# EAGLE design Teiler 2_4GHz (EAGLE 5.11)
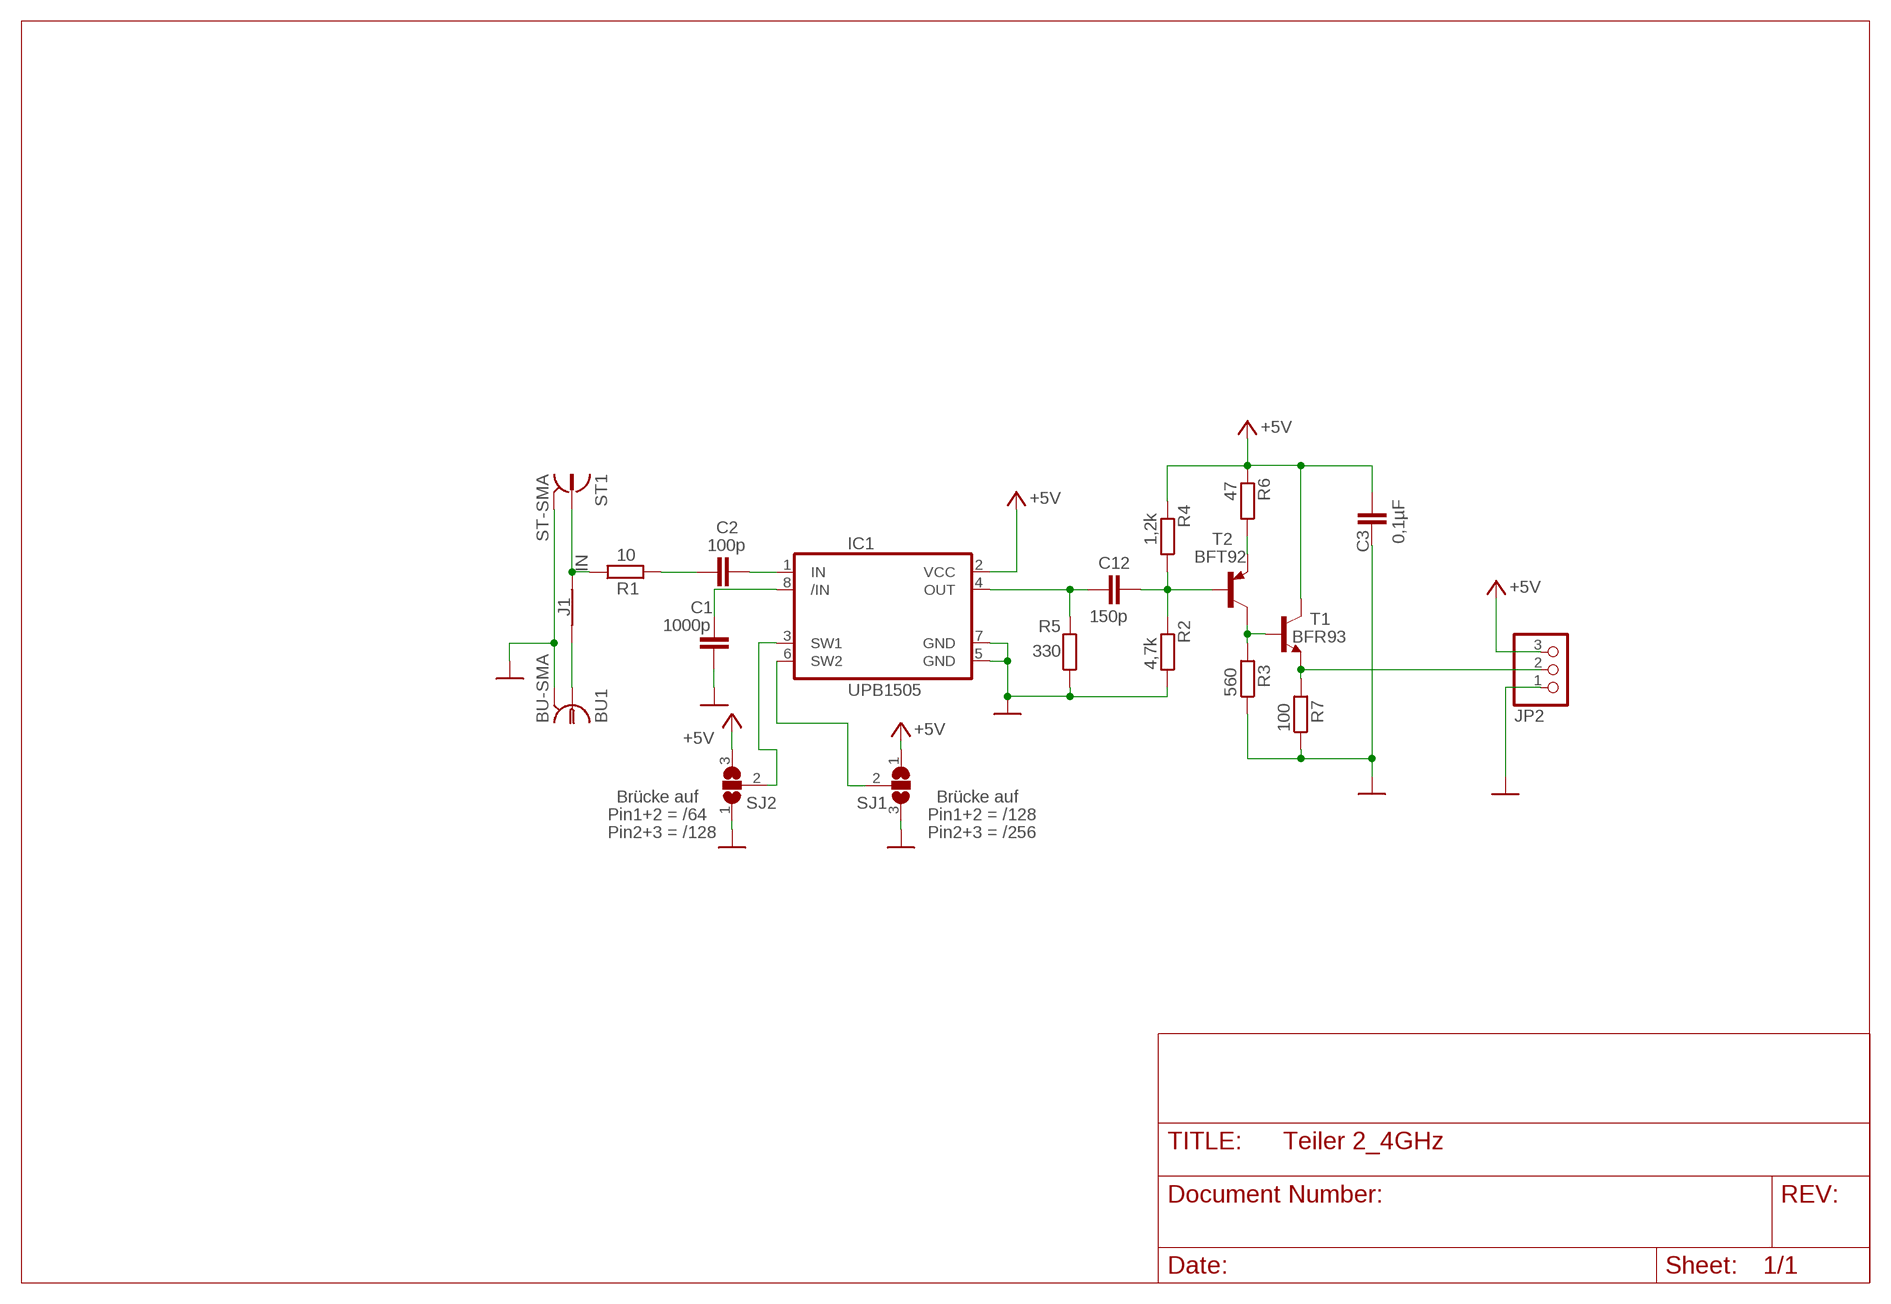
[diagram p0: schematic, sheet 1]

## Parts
BU1  BU-SMA  BU.SMA-L  [BU-SMA-L]
C1  1000p  C-EUC0805  [C0805]
C2  100p  C-EUC0805  [C0805]
C3  0,1µF  C-EUC0805  [C0805]
C12  150p  C-EUC0805  [C0805]
IC1  UPB1505  [SO8]
J1  IN  VORTEILER_IN  [VORT_JUMPER]
JP2  PINHD-1X03_2.54-SMD-90°  [1X03SMD/90]
R1  10  R-EU_M1206  [M1206]
R2  4,7k  R-EU_R0805  [R0805]
R3  560  R-EU_R0805  [R0805]
R4  1,2k  R-EU_R0805  [R0805]
R5  330  R-EU_R0805  [R0805]
R6  47  R-EU_R0805  [R0805]
R7  100  R-EU_R0805  [R0805]
SJ1  SJ2W  [SJ_2]
SJ2  SJ2W  [SJ_2]
ST1  ST-SMA  ST-BNC-L  [ST-SMA-L]
T1  BFR93  BFR93-NPN-SOT23-BEC  [SOT23-BEC]
T2  BFT92  BC807-16-PNP-SOT23-BEC  [SOT23-BEC]

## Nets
+5V: C3.1 IC1.2(VCC) JP2.3 R4.2 R6.2 SJ1.1 SJ2.3 T1.C
GND: BU1.GND C1.1 C3.2 IC1.5(GND) IC1.7(GND) JP2.1 R2.1 R3.1 R5.1 R7.1 SJ1.3 SJ2.1 ST1.GND
N$1: C1.2 IC1.8(/IN)
N$2: C12.2 IC1.4(OUT) R5.2
N$3: BU1.1 J1.GND@1
N$4 [Abstand1]: J1.GND@2 R1.1 ST1.1
N$5: C2.1 IC1.1(IN)
N$6: C12.1 R2.2 R4.1 T2.B
N$8: C2.2 R1.2
N$9: R3.2 T1.B T2.C
N$10: IC1.6(SW2) SJ1.2
N$11: R6.1 T2.E
N$12: IC1.3(SW1) SJ2.2
OUT: JP2.2 R7.2 T1.E

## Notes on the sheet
- Brücke auf | Brücke auf
- Pin1+2 = /64 | Pin1+2 = /128
- Pin2+3 = /128 | Pin2+3 = /256

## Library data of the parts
BU1 = 1Eigene:BU.SMA-L
C1-C3 C12 = rcl:C-EU: CAPACITOR, European symbol
IC1 = 1Eigene:UPB1505
J1 = 1Eigene:VORTEILER_IN
JP2 = pinhead-2:PINHD-1X03: PIN HEADER
R1-R7 = rcl:R-EU_: RESISTOR, European symbol
SJ1 SJ2 = jumper:SJ2W: SMD solder JUMPER
ST1 = 1Eigene:ST-BNC-L
T1 = transistor-neu-to92:*-NPN-: NPN Transistror
T2 = transistor:*-PNP-: PNP Transistror

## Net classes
1 Abstand1: width 0.1 mm, drill 0.6 mm, clearance 2 mm

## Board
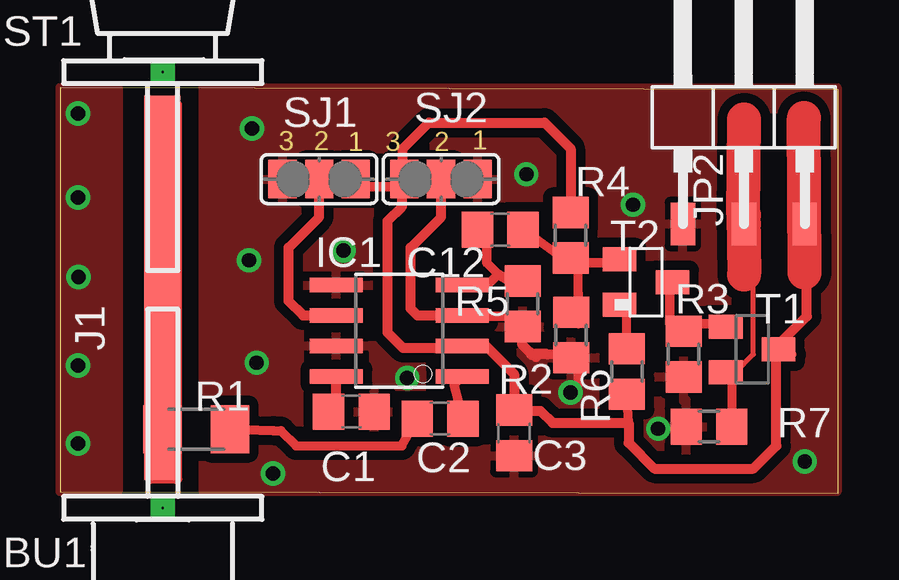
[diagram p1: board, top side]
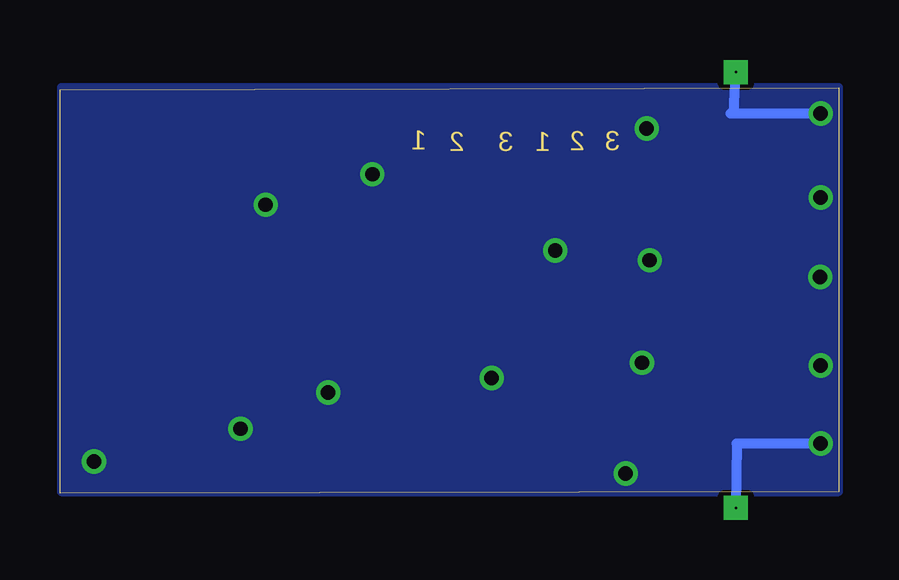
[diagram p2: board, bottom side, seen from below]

Size 32.43 x 16.89 mm. Coordinates in mm from the lower left corner, seen from the top.
Outline: 0,0.07 32.43,0 32.43,16.81 0,16.89 0,0.07
Copper layers (1*16): Top 0.035mm / dielectric 1.5mm / Bottom 0.035mm
Design rules "default *": minimum track width 0.4mm, minimum drill 0.7mm, track to track 0.4mm, track to pad 0.4mm, pad to pad 0.4mm, via to via 0.4mm, smd to smd 0.4mm, copper to edge 0mil, drill to drill 8mil, minimum pad ring 10mil, minimum via ring 8mil, stop-mask expansion 4mil, vias tented up to drill 0mil, thermal gap 10mil

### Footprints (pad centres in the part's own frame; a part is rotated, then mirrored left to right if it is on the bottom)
BU-SMA-L = smd 0.635 x 1.27: 1 -5.08,0 | drill 0.1 pad 1 square: GND 2.554,0
C0805 = smd 1.3 x 1.5: 1 -0.95,0; 2 0.95,0
SO8 = smd 0.61 x 2.21: 1 -1.905,-2.616; 2 -0.635,-2.616; 3 0.635,-2.616; 4 1.905,-2.616; 5 1.905,2.616; 6 0.635,2.616; 7 -0.635,2.616; 8 -1.905,2.616
VORT_JUMPER = smd 8 x 1.5: GND@1 -4,0; GND@2 4,0
1X03SMD/90 = smd 1.016 x 1.778: 1 -1.27,-5.08; 2 1.27,-5.08; 3 3.81,-5.08
M1206 = smd 1.6 x 2: 1 -1.4,0; 2 1.4,0
R0805 = smd 1.3 x 1.5: 1 -0.95,0; 2 0.95,0
SJ_2 = smd 1.168 x 1.6: 1 -1.524,0; 2 0,0; 3 1.524,0
ST-SMA-L = smd 0.635 x 1.27: 1 -3.81,0 | drill 0.1 pad 1 square: GND 3.824,0
SOT23-BEC = smd 1 x 1.4: B -0.95,-1.1; C 0,1.1; E 0.95,-1.1

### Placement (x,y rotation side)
BU1  4.28,1.95 270 top
C1  12.14,3.41 180 top
C2  15.84,3.12 180 top
C3  18.92,2.52 270 top
C12  18.34,10.98 180 top
IC1  14.13,6.78 90 top
J1  4.25,8.57 90 top
JP2  27.22,16.3 0 top
R1  5.68,2.67 0 top
R2  21.3,6.6 90 top
R3  25.98,5.8 90 top
R4  21.27,10.75 90 top
R5  19.27,7.9 90 top
R6  23.62,5.08 270 top
R7  27.04,2.78 0 top
SJ1  10.79,13.09 180 top
SJ2  15.88,13.09 180 top
ST1  4.28,13.73 90 top
T1  28.84,6 270 top
T2  24.42,8.8 270 top

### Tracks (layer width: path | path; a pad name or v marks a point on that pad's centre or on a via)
+5V
  Top 0.381: IC1.2 17.75,6.14 | 23.69,2.93 R6.2
  Top 0.4: T1.C 30.48,5.79 | R6.2 24.13,4.52 | SJ1.1 12.7,12.77 13.97,12.77 SJ2.3
  Top 0.406: 17.75,6.14 18.92,4.97 C3.1 18.95,3.44 20.02,3.44 20.53,2.93 23.69,2.93 23.69,2.1 24.77,1.03 28.89,1.03 29.84,1.98 29.84,5.91 T1.C 29.94,6.2 31.11,7.38 31.11,11.14 JP2.3 31.02,9.21 | R4.2 21.43,11.86 | IC1.2 16.68,6.07 14.29,6.07 13.65,6.7 13.65,11.35 14.25,11.95 14.25,12.49 13.97,12.77 | R4.2 21.79,11.71 | SJ2.3 14.29,13.16 14.29,14.36 15.37,15.44 20.19,15.44 21.27,14.36 R4.2
  Top 1.422: 31.02,9.21 31,15.64
GND  (via drill 0.6)
  Top 0.4: 16.51,7.41 16.51,7.38 19.05,7.38 R5.1 19.05,7.06 | 21.59,5.79 21.59,4.52 v21.27,4.2 | 21.59,5.79 20.32,5.79 | 21.59,5.79 R2.1
  Top 0.406: 20.32,5.79 19.62,5.79 19.84,5.69 19.52,5.94 19.27,6.19 19.27,6.82 19.02,7.07 19.14,7.07
  Bottom 0.406: v0.75,15.82 4.38,15.82 | 4.38,15.82 4.5,15.82 | 4.38,15.82 ST1.GND | 4.12,-0.48 BU1.GND 4.25,2.08 v0.75,2.08
  other vias: 0.77,9.01 0.75,12.32 0.75,5.33 8,15.2 8.19,5.44 8.88,0.82 14.46,4.81 31.03,1.32 7.88,9.71 23.88,12.02 24.92,2.69 19.43,13.29 11.81,10.12
  pour Bottom: 0,16.9 32.38,16.9 32.38,0.07 0,0.07
  pour Top: 5.96,16.9 32.38,16.9 32.38,0.07 5.96,0.07
  pour Top: 0,16.9 2.42,16.9 2.42,0.07 0,0.07
N$1
  Top 0.406: C1.2 11.52,3.41 IC1.8
N$2
  Top 0.381: IC1.4 17.81,8.68 18.26,9.12
  Top 0.4: R5.2 19.05,8.65 18.26,9.12 17.78,9.6 17.78,10.87 C12.2
N$3
  Top 0.406: J1.GND@1 BU1.1
N$4
  Top 0.4: 3.75,11.5 3.81,11.5 J1.GND@2
  Top 0.406: 4.88,3.18 R1.1 | 4.88,3.18 4.88,9.82 | 4.88,9.82 4.88,16.2 3.75,16.2 3.75,11.5 3.75,0.6 4.88,0.6 | 4.88,0.6 4.88,0.57 | 4.88,0.6 4.88,3.18 | 4.88,9.82 4.38,9.82 ST1.1 4.25,9.89
N$5
  Top 0.381: C2.1 16.41,4.53 IC1.1
N$6
  Top 0.381: 21.59,8.33 21.59,9.49 R4.1 20.6,10.05 C12.1
  Top 0.4: T2.B 22.86,9.6 21.59,9.6 R4.1 | 21.59,8.33 21.59,7.06 R2.2 | C12.1 19.05,10.87
N$8
  Top 0.381: 8.89,2.62 9.21,2.62 9.84,1.98 14.24,1.98 C2.2
  Top 0.4: R1.2 8.89,2.62
N$9
  Top 0.4: T1.B 27.94,7.06 26.67,7.06 R3.2 25.4,7.06 25.4,8.33 T2.C
N$10
  Top 0.406: IC1.6 10.13,7.41 9.53,8.01 9.53,10.23 10.79,11.5 SJ1.2
N$11
  Top 0.381: R6.1 23.62,7.55 T2.E
  Top 0.4: R6.1 24.13,5.79
N$12
  Top 0.406: IC1.3 14.89,7.41 14.61,7.7 14.61,10.23 15.88,11.5 SJ2.2
OUT
  Top 0.2: T1.E 28.15,5.05 28.89,5.79 28.89,10.82 JP2.2
  Top 0.381: R7.2 27.99,4.8 T1.E
  Top 1.422: 28.48,11.6 28.5,9.12 | 28.48,11.6 28.5,15.57 | JP2.2 28.49,11.59 28.48,11.6

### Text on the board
Milling: 3 | 2 | 1 | 3 | 2 | 1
